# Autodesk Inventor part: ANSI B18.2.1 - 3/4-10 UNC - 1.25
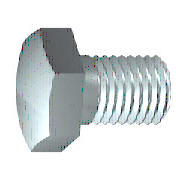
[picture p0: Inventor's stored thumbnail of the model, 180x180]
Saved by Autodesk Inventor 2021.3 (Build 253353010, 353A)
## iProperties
IsCustomPart: 0
Created: 2018-01
Part Number: ANSI B18.2.1 - 3/4-10 UNC - 1.25
Material: Steel, Mild
Description: Heavy Hex Bolt
Document SubType Name: Modeling
Standard: ANSI B18.2.1
Designer: u1426
Standard Revision: 1996
Standards Organization: ANSI
Language: en-US
Size Designation: 3/4-10 UNC - 1.25
Categories: <MemberInstance><Categories><Category DisplayName="Fasteners" InternalName="e4da775c-781d-43d5-af7c-5136215cf5a6" Mnemonic="FSTN"><Category DisplayName="Bolts"
Density: 7.85 g/cm^3
Appearance: Semi-Polished
Author: u1426
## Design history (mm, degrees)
sketch "Sketch1"
  geometry: L1 (0, 9.525)-(393.7, 9.525); L2 (393.7, 9.525)-(393.7, 0); L3 (393.7, 0)-(0, 0); L4 (-88.9, 0)-(533.4, 0) reference; L5 (0, -1.905)-(0, 11.43) reference; L6 (0, 9.525)-(0, 0)
  constraints: 8 end point, 3 point on line, 1 collinear
  dimensions: "d2" = 19.05 diameter of L1 L3 (= GD); "d59" = 393.7 distance between parallel lines of L2 L5 (= NLG)
revolve "Body" sketch "Sketch1" stored, may be unused: angle "d12" = 90 deg
sketch "Sketch2"
  geometry: L1 (0, 18.331)-(15.875, 9.165); L2 (15.875, 9.165)-(15.875, -9.165); L3 (15.875, -9.165)-(0, -18.331); L4 (0, -18.331)-(-15.875, -9.165); L5 (-15.875, -9.165)-(-15.875, 9.165); L6 (-15.875, 9.165)-(0, 18.331); L7 (-22.225, 0)-(22.225, 0) reference; L8 (0, 25.663)-(0, -25.663) reference; 2 further points
  constraints: 12 end point, 2 midpoint, 1 coincident, 1 vertical, 11 other
  dimensions: "d11" = 31.75 distance between parallel lines of L5 L2 (= SW)
extrude "Head" join sketch "Sketch2" distance "d3" = 12.7 (= KOH); taper "d4" = 0 deg
revolve "Chamfer1" stored, may be unused: angle "d21" = 90 deg
workplane "Work Plane1"
body "Solid1"
feature "Thread" dims "d15" = 127 (= GEL), "d16" = 0
chamfer "Chamfer2" distance "d6" = 1.51257 (= -0.5 x SPD + 0.5 x GD); stored, may be unused: second distance "d7" = 1.51267 (computed from GUL), angle "d55" = 45 deg
fillet "Fillet" dims "d71" = 1.524 (= RR)
sketch "Sketch4"
  geometry: L1 (-10.867, 19.05)-(-12.7, 15.875); L2 (-1.1, 0)-(-0.234, 0); L3 (-15.193, 0)-(2.259, 0) reference; L4 (-12.7, 19.05)-(-10.867, 19.05); L5 (-12.7, 15.875)-(-12.7, 19.05); L6 (0, 22.86)-(0, -3.81) reference
  constraints: 8 end point, 1 parallel, 1 perpendicular, 1 point on line
  dimensions: "d65" = 31.75 diameter of L1.end L2 (= SW); "d67" = 30 deg angle of L1 L5 (= ANG1); "d68" = 38.1 diameter of L4 L2 (= 1.2 x SW); "d69" = 12.7 distance between parallel lines of L5 L6 (= KOH)
other parameters: "NLG" = 393.7 [user parameter; used in 1 equation term], "GD" = 19.05 [user parameter; used in 2 equation terms], "BDM" = 19.5072 [user parameter; used in 1 equation term], "KOH" = 12.7 [user parameter; used in 2 equation terms], "GEL" = 127 [user parameter; used in 1 equation term], "SW" = 31.75 [user parameter; used in 5 equation terms], "SW0" = 31.75 (= SW) [user parameter], "SPD" = 16.02486 [user parameter; used in 1 equation term], "SD2" = 19.5072 (= BDM) [user parameter], "SD" = 0 [user parameter], "ANG1" = 30 deg [user parameter; used in 1 equation term], "GAL" = 1.51257 (= GUL) [user parameter], "GUL" = 1.51257 [user parameter; used in 2 equation terms], "d8" = 0, "RR" = 1.524 [user parameter; used in 1 equation term], "d58" = 0, "RR1" = 0.1 [user parameter], "d73" = 0, "THREADDIA" = 19.05 [user parameter], "TOA" = 30 deg [user parameter], "PTC" = 2.54 (computed from TPU) [user parameter], "NND" = 19.05 [user parameter], "E0" = 36.67125 (= 1.155 x SW) [user parameter], "SLG" = 0 [user parameter], "GD1" = 16.02486 [user parameter]
